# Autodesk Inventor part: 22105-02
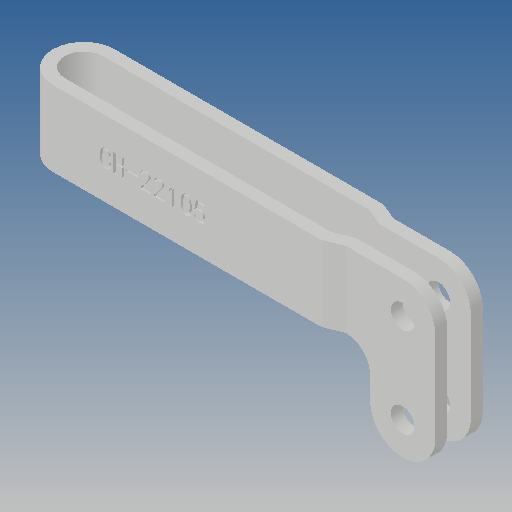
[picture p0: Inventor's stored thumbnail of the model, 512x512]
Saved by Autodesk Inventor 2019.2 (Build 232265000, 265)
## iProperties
Created: 2017-06
Part Number: 22105-02
Material: Ogólny
Document SubType Name: Modeling
Designer: CADENGINEERING4
Density: 1 g/cm^3
Appearance: Domyślna
Author: CADENGINEERING4
Revision Number: ÈÎºÎ
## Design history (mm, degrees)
feature "ÇÐ³ý-À­Éì4"
node "Bryła1"
